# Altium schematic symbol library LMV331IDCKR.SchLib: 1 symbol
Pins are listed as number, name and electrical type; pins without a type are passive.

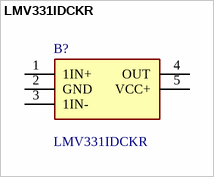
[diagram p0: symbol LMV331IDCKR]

## LMV331IDCKR
designator B?
Texas Instruments LMV331IDCKR Comparator, Open Collector O/P, 2.7  5.5 V 5-Pin SC-70; Geometry.Height: 1.1mm
footprint SOT65P210X110-5N
pins: 1 1IN+, 2 GND, 3 1IN-, 4 OUT, 5 VCC+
